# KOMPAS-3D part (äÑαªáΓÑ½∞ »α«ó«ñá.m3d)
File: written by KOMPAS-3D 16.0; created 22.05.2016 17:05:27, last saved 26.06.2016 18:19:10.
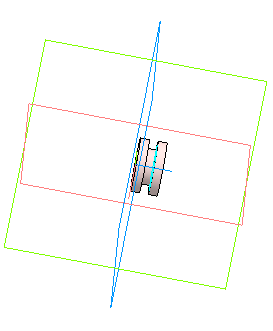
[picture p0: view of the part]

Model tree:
1. Эскиз:1
2. Операция выдавливания:1
     Расстояние 1 = 6
3. Смещенная плоскость:1
     Расстояние = 2
4. Эскиз:2
5. Вырезать элемент выдавливания:1
     Расстояние 1 = 2
6. Эскиз:3
7. Вырезать элемент выдавливания:2
     Расстояние 1 = 14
